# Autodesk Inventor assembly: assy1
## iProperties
Author: Administrator
Created: 2001-01
Part Number: assy1
Document SubType Name: Assembly
Designer: Administrator
Control State: 0
Master: False
Checked Out: False
PropertySet Name: Design Tracking Control
Shininess: 0.0
PropertySet Name: _Private Model Information
Density: 0.0
Volumn: 0.0
Area: 0.0
PropertySet Name: Model Information
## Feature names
1. 珖
2. 珖
